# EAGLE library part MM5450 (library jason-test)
MM5450 34-segment LED driver
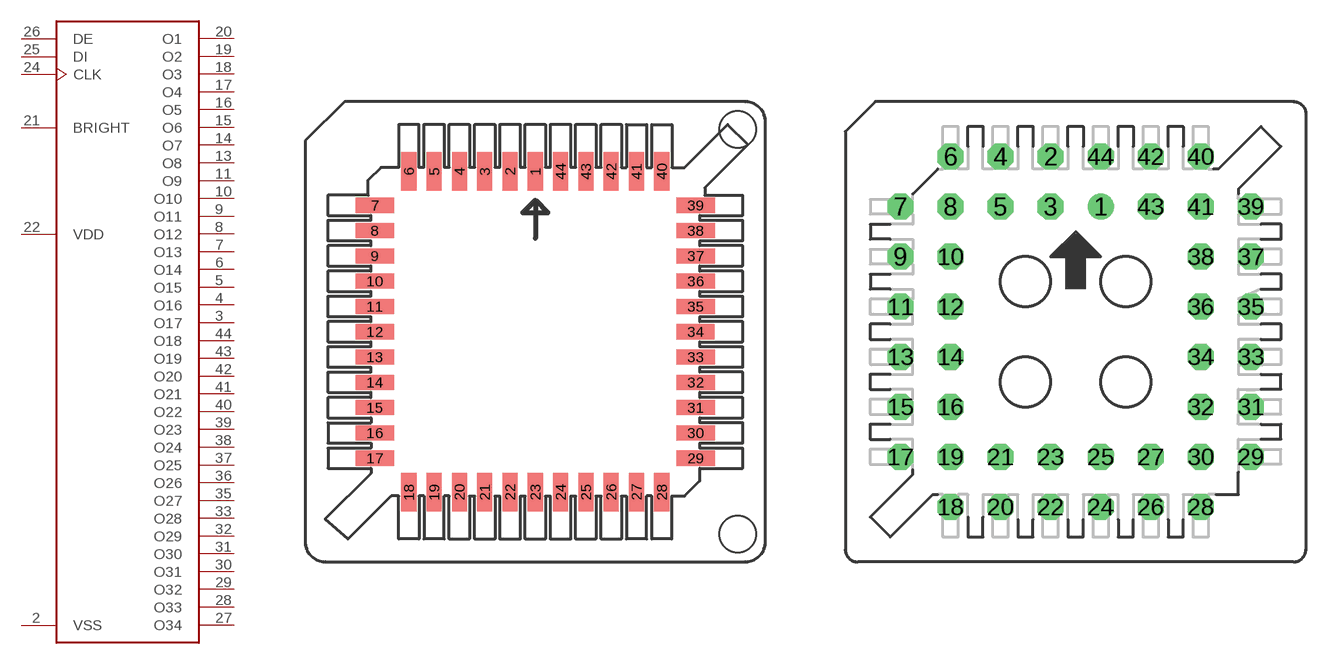
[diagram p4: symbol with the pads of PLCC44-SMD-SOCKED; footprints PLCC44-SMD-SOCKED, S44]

Designator prefix U

## MM5450  [PLCC44-SMD-SOCKED]
2  VSS  pwr
3  O17  out
4  O16  out
5  O15  out
6  O14  out
7  O13  out
8  O12  out
9  O11  out
10  O10  out
11  O9  out
13  O8  out
14  O7  out
15  O6  out
16  O5  out
17  O4  out
18  O3  out
19  O2  out
20  O1  out
21  BRIGHT  pwr
22  VDD  pwr
24  CLK  in
25  DI  in
26  DE  in
27  O34  out
28  O33  out
29  O32  out
30  O31  out
31  O30  out
32  O29  out
33  O28  out
35  O27  out
36  O26  out
37  O25  out
38  O24  out
39  O23  out
40  O22  out
41  O21  out
42  O20  out
43  O19  out
44  O18  out

## MM54501  [S44]
Pads as for PLCC44-SMD-SOCKED

## MM54502  [3M44]
Pads as for PLCC44-SMD-SOCKED

## MM54503  [PLCC44S]
Pads as for PLCC44-SMD-SOCKED

## MM54504  [PLCC-44-SMT-TT]
Pads as for PLCC44-SMD-SOCKED

## Footprint PLCC44-SMD-SOCKED (pad centres in mm)
PLCC-SMD Fassung / sockets Source: http://www.mpegarry.de/pdf/p112-113.pdf
smd 0.76 x 1.91: 1 0,8.055; 2 -1.27,8.055; 3 -2.54,8.055; 4 -3.81,8.055; 5 -5.08,8.055; 6 -6.35,8.055; 18 -6.35,-8.055; 19 -5.08,-8.055; 20 -3.81,-8.055; 21 -2.54,-8.055; 22 -1.27,-8.055; 23 0,-8.055; 24 1.27,-8.055; 25 2.54,-8.055; 26 3.81,-8.055; 27 5.08,-8.055; 28 6.35,-8.055; 40 6.35,8.055; 41 5.08,8.055; 42 3.81,8.055; 43 2.54,8.055; 44 1.27,8.055
smd 1.91 x 0.76: 7 -8.055,6.35; 8 -8.055,5.08; 9 -8.055,3.81; 10 -8.055,2.54; 11 -8.055,1.27; 12 -8.055,0; 13 -8.055,-1.27; 14 -8.055,-2.54; 15 -8.055,-3.81; 16 -8.055,-5.08; 17 -8.055,-6.35; 29 8.055,-6.35; 30 8.055,-5.08; 31 8.055,-3.81; 32 8.055,-2.54; 33 8.055,-1.27; 34 8.052,0; 35 8.055,1.27; 36 8.055,2.54; 37 8.055,3.81; 38 8.055,5.08; 39 8.055,6.35

## Footprint S44 (pad centres in mm)
PLCC SOCKET
drill 0.813 round: 1 1.27,6.35
drill 0.813 octagon: 2 -1.27,8.89; 3 -1.27,6.35; 4 -3.81,8.89; 5 -3.81,6.35; 6 -6.35,8.89; 7 -8.89,6.35; 8 -6.35,6.35; 9 -8.89,3.81; 10 -6.35,3.81; 11 -8.89,1.27; 12 -6.35,1.27; 13 -8.89,-1.27; 14 -6.35,-1.27; 15 -8.89,-3.81; 16 -6.35,-3.81; 17 -8.89,-6.35; 18 -6.35,-8.89; 19 -6.35,-6.35; 20 -3.81,-8.89; 21 -3.81,-6.35; 22 -1.27,-8.89; 23 -1.27,-6.35; 24 1.27,-8.89; 25 1.27,-6.35; 26 3.81,-8.89; 27 3.81,-6.35; 28 6.35,-8.89; 29 8.89,-6.35; 30 6.35,-6.35; 31 8.89,-3.81; 32 6.35,-3.81; 33 8.89,-1.27; 34 6.35,-1.27; 35 8.89,1.27; 36 6.35,1.27; 37 8.89,3.81; 38 6.35,3.81; 39 8.89,6.35; 40 6.35,8.89; 41 6.35,6.35; 42 3.81,8.89; 43 3.81,6.35; 44 1.27,8.89

## Footprint 3M44 (pad centres in mm)
PLCC SOCKET
drill 0.813 round: 1 1.27,6.35
drill 0.813 octagon: 2 -1.27,8.89; 3 -1.27,6.35; 4 -3.81,8.89; 5 -3.81,6.35; 6 -6.35,8.89; 7 -8.89,6.35; 8 -6.35,6.35; 9 -8.89,3.81; 10 -6.35,3.81; 11 -8.89,1.27; 12 -6.35,1.27; 13 -8.89,-1.27; 14 -6.35,-1.27; 15 -8.89,-3.81; 16 -6.35,-3.81; 17 -8.89,-6.35; 18 -6.35,-8.89; 19 -6.35,-6.35; 20 -3.81,-8.89; 21 -3.81,-6.35; 22 -1.27,-8.89; 23 -1.27,-6.35; 24 1.27,-8.89; 25 1.27,-6.35; 26 3.81,-8.89; 27 3.81,-6.35; 28 6.35,-8.89; 29 8.89,-6.35; 30 6.35,-6.35; 31 8.89,-3.81; 32 6.35,-3.81; 33 8.89,-1.27; 34 6.35,-1.27; 35 8.89,1.27; 36 6.35,1.27; 37 8.89,3.81; 38 6.35,3.81; 39 8.89,6.35; 40 6.35,8.89; 41 6.35,6.35; 42 3.81,8.89; 43 3.81,6.35; 44 1.27,8.89
hole 1.499 at -8.89,8.89

## Footprint PLCC44S (pad centres in mm)
PLASTIC LEADED CHIP CARRIER square
smd 0.6 x 2.2: 1 0,8.1; 2 -1.27,8.1; 3 -2.54,8.1; 4 -3.81,8.1; 5 -5.08,8.1; 6 -6.35,8.1; 18 -6.35,-8.1; 19 -5.08,-8.1; 20 -3.81,-8.1; 21 -2.54,-8.1; 22 -1.27,-8.1; 23 0,-8.1; 24 1.27,-8.1; 25 2.54,-8.1; 26 3.81,-8.1; 27 5.08,-8.1; 28 6.35,-8.1; 40 6.35,8.1; 41 5.08,8.1; 42 3.81,8.1; 43 2.54,8.1; 44 1.27,8.1
smd 2.2 x 0.6: 7 -8.1,6.35; 8 -8.1,5.08; 9 -8.1,3.81; 10 -8.1,2.54; 11 -8.1,1.27; 12 -8.1,0; 13 -8.1,-1.27; 14 -8.1,-2.54; 15 -8.1,-3.81; 16 -8.1,-5.08; 17 -8.1,-6.35; 29 8.1,-6.35; 30 8.1,-5.08; 31 8.1,-3.81; 32 8.1,-2.54; 33 8.1,-1.27; 34 8.1,0; 35 8.1,1.27; 36 8.1,2.54; 37 8.1,3.81; 38 8.1,5.08; 39 8.1,6.35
